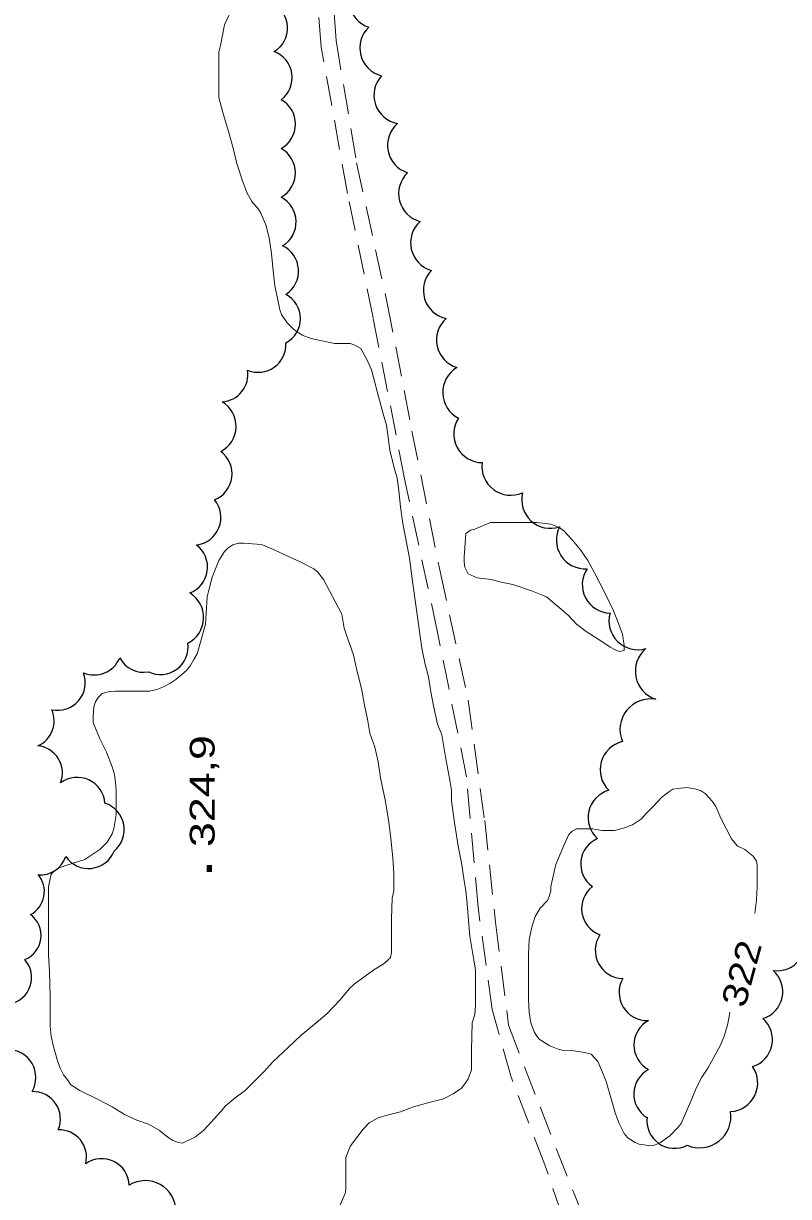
# Model space of a CAD drawing. Extents: x 240591 to 242335, y 5323482 to 5326937.
# Drawn here: x 241626.7 to 241719.3, y 5325779.2 to 5325921.4 of the extents above; entities that cross this region are included whole.
import ezdxf

# ---------------------------------------------------------------- set-up
doc = ezdxf.new("R2010")
doc.units = 0
doc.header["$LTSCALE"] = 1.2
doc.linetypes.add('MEDIUM_DASHED', pattern=[4.5, 3, -1.5])
for name, color, linetype, lineweight in [('19', 7, 'Continuous', 13), ('2', 7, 'Continuous', 13), ('3', 7, 'Continuous', 140), ('44', 7, 'Continuous', 25)]:
    doc.layers.add(name, color=color, linetype=linetype, lineweight=lineweight)

msp = doc.modelspace()

# ---------------------------------------------------------------- linework, layer by layer
at = {"layer": '19', "linetype": 'MEDIUM_DASHED'}
for points in [[(241695.4, 5325766.6), (241689.8, 5325783.1), (241685.7, 5325793.7), (241683.4, 5325801.9), (241681.7, 5325814.3), (241680.3, 5325830.1), (241676.8, 5325847.6), (241672.8, 5325866.2), (241669, 5325885.7), (241665.9, 5325900.8), (241662.7, 5325918.5), (241661.5, 5325935.1), (241659.9, 5325951.9), (241658.8, 5325968), (241656.9, 5325986.2), (241654.9, 5326006.1), (241652.6, 5326024.1), (241650, 5326039.6), (241647, 5326053.6), (241643.4, 5326064.5), (241638.5, 5326075.3), (241632.4, 5326086.8), (241627, 5326097.8)], [(241663.5, 5325933.4), (241664.5, 5325919.3), (241667, 5325904.5), (241670.7, 5325887.5), (241673.7, 5325872), (241677.1, 5325855), (241680.5, 5325839.4), (241682.5, 5325824.8), (241683.8, 5325812.5), (241685.4, 5325800), (241689.2, 5325790.1), (241693.4, 5325779.4), (241696.7, 5325771.1), (241698.6, 5325766.6)]]:
    msp.add_lwpolyline(points, dxfattribs=at)
at = {"layer": '2'}
for points in [[(241664.3, 5325882.6), (241661.5, 5325883.2), (241660.4, 5325883.6), (241659.4, 5325884.3), (241658.6, 5325885.1), (241657.9, 5325886.1), (241657.7, 5325886.7), (241657.4, 5325888.1), (241657.1, 5325889.6), (241656.9, 5325891.4), (241656.7, 5325893.5), (241656.4, 5325895.4), (241656, 5325897), (241655.4, 5325898.4), (241655.1, 5325898.9), (241654.3, 5325899.8), (241653.7, 5325900.9), (241653.2, 5325902.2), (241652.5, 5325904.4), (241652.1, 5325906.1), (241651.6, 5325907.9), (241650.8, 5325910.6), (241650.3, 5325912.4), (241650.3, 5325913.3), (241650.3, 5325915.2), (241650.3, 5325917.9), (241650.5, 5325918.7), (241651, 5325921.2), (241651.6, 5325922.5)], [(241664.6, 5325777.3), (241665.6, 5325779.6), (241665.7, 5325780.1), (241665.7, 5325781.4), (241665.7, 5325784), (241666.2, 5325785.3), (241666.5, 5325785.7), (241667.8, 5325787.4), (241668.5, 5325788.2), (241669.6, 5325788.8), (241670.7, 5325789.1), (241672.3, 5325789.5), (241673.9, 5325790.1), (241675.9, 5325790.7), (241677.5, 5325791.1), (241678.7, 5325791.7), (241679.7, 5325792.4), (241680.1, 5325792.9), (241680.5, 5325793.5), (241680.9, 5325794.6), (241680.9, 5325795.3), (241680.9, 5325797), (241681, 5325800.3), (241681.3, 5325801.3), (241681.4, 5325802.4), (241681.4, 5325803.7), (241681.4, 5325806.7), (241681.2, 5325807.9), (241680.7, 5325810.8), (241680.6, 5325812.2), (241680.4, 5325814.7), (241680.2, 5325816.3), (241680, 5325817.5), (241679.7, 5325819.7), (241679.3, 5325821.7), (241678.8, 5325824.8), (241678.5, 5325827.2), (241678.5, 5325828.5), (241678.3, 5325829.7), (241677.8, 5325832.3), (241677.3, 5325835.2), (241676.8, 5325836.5), (241676.3, 5325838.7), (241676, 5325840.4), (241675.7, 5325842.2), (241675.3, 5325843.7), (241674.9, 5325845.7), (241674.7, 5325847.1), (241674.4, 5325849.2), (241674.2, 5325850.6), (241673.8, 5325853.5), (241673.4, 5325856.6), (241673.1, 5325858.1), (241672.6, 5325860.8), (241672.3, 5325862.8), (241672.1, 5325864.8), (241671.9, 5325866.3), (241671.5, 5325867.7), (241671, 5325869.7), (241670.8, 5325871.2), (241670.6, 5325872.7), (241670.2, 5325874.1), (241669.5, 5325876.8), (241668.8, 5325879.4), (241668.3, 5325880.5), (241667.5, 5325882), (241666.8, 5325882.4), (241666.2, 5325882.6), (241665.4, 5325882.6), (241664.3, 5325882.6)], [(241646.4, 5325843), (241646.9, 5325843.6), (241647.3, 5325844.3), (241647.7, 5325845), (241648.1, 5325846.4), (241648.7, 5325848.6), (241648.8, 5325849.9), (241648.9, 5325851.9), (241649.1, 5325852.7), (241649.5, 5325854.3), (241650.3, 5325856.3), (241651, 5325857.4), (241651.4, 5325857.8), (241652, 5325858.2), (241652.7, 5325858.4), (241653.4, 5325858.4), (241654.9, 5325858.3), (241655.6, 5325858.2), (241657, 5325857.6), (241658.9, 5325856.7), (241660.1, 5325856.2), (241661.8, 5325855.3), (241662.3, 5325854.9), (241663, 5325854), (241665.2, 5325849.8)], [(241665.2, 5325849.8), (241665.5, 5325848.1), (241665.7, 5325847.5), (241666.6, 5325844.9), (241667, 5325843.2), (241667.6, 5325840.8), (241668, 5325838.6), (241668.3, 5325837.1), (241668.6, 5325835.4), (241669.2, 5325833.7), (241669.6, 5325831.9), (241669.9, 5325830), (241670.5, 5325827.1), (241670.9, 5325824.6), (241671.1, 5325823), (241671.4, 5325820.3), (241671.5, 5325818.4), (241671.5, 5325816.3), (241671.3, 5325815.4), (241671.2, 5325812.9), (241671.2, 5325811.5), (241671.2, 5325810.1), (241671.2, 5325808.8), (241671.1, 5325808.2), (241670.7, 5325807.8), (241670.2, 5325807.4), (241669.1, 5325806.7), (241666.7, 5325805), (241666.1, 5325804.4), (241665, 5325803.1), (241663.4, 5325801.4), (241662.1, 5325800.3), (241660.3, 5325798.8), (241658.7, 5325797.3), (241656.9, 5325795.6), (241655.8, 5325794.4), (241653.5, 5325792.1), (241652.3, 5325791.2), (241651.1, 5325790.2), (241650.6, 5325789.6), (241648.5, 5325787.3), (241647.5, 5325786.5), (241645.9, 5325785.7), (241645.4, 5325785.8), (241644.7, 5325786.1), (241644.2, 5325786.4), (241643.1, 5325787.3), (241641.8, 5325788), (241640.4, 5325788.5), (241638.9, 5325789.2), (241637.4, 5325790.1), (241635.7, 5325791), (241633.5, 5325792.1), (241632.4, 5325792.8), (241632, 5325793.4), (241631.5, 5325794), (241631.1, 5325794.8), (241630.8, 5325795.7), (241630.2, 5325797.7), (241630, 5325798.7), (241629.9, 5325799.9), (241629.9, 5325801), (241629.9, 5325803.4), (241629.8, 5325806.5), (241629.7, 5325808.5), (241629.7, 5325810.8), (241629.7, 5325813.3), (241629.7, 5325816.8), (241630, 5325818.3), (241630.5, 5325818.8), (241631.1, 5325819.1), (241631.9, 5325819.4), (241634.1, 5325820.1), (241634.7, 5325820.5), (241635.9, 5325821.3), (241636.8, 5325822.2), (241637.4, 5325823.2), (241637.6, 5325823.8), (241637.9, 5325825.5), (241637.9, 5325826.5), (241637.9, 5325828.5), (241637.8, 5325829.4), (241637.7, 5325830.4), (241637.4, 5325831.3), (241636.7, 5325833.1), (241635.9, 5325834.7), (241635.1, 5325836.7), (241635.1, 5325837.4), (241635.2, 5325838.6), (241635.4, 5325839.2), (241635.7, 5325839.7), (241636.2, 5325840.2), (241636.9, 5325840.4), (241637.8, 5325840.5), (241638.8, 5325840.5), (241641.9, 5325840.5), (241642.8, 5325840.7), (241643.6, 5325841), (241644.4, 5325841.4), (241645.1, 5325841.9), (241646.4, 5325843)], [(241691.1, 5325819.5), (241692.1, 5325821.8), (241692.7, 5325823.1), (241693.1, 5325823.5), (241693.6, 5325823.8), (241694.2, 5325823.8), (241695.6, 5325823.8), (241696.7, 5325823.6), (241698.2, 5325823.6), (241699.3, 5325823.9), (241700.4, 5325824.3), (241701.5, 5325825), (241702, 5325825.6), (241702.9, 5325826.5), (241703.9, 5325827.6), (241704.8, 5325828.3), (241705.3, 5325828.6), (241705.9, 5325828.7), (241707, 5325828.8), (241708.1, 5325828.6), (241708.7, 5325828.4), (241709.2, 5325828.1), (241710.1, 5325827.1), (241710.5, 5325826.5), (241711.1, 5325825.1), (241712.4, 5325822.6), (241713.1, 5325821.7), (241713.6, 5325821.5), (241714, 5325821.3), (241715, 5325820.5), (241715.4, 5325819.9), (241715.5, 5325819.4), (241715.5, 5325818.8), (241715.5, 5325816.8), (241715.4, 5325815.2), (241715.2, 5325813.6)], [(241712.2, 5325801.6), (241712.2, 5325801.5), (241711.9, 5325800), (241711.5, 5325798.7), (241711, 5325797.5), (241710.4, 5325796.4), (241709.5, 5325794.8), (241708.8, 5325793.7), (241708.1, 5325792.4), (241707.6, 5325791.1), (241706.3, 5325788.1), (241705.9, 5325787.6), (241704.9, 5325786.6), (241703.8, 5325785.8), (241703.2, 5325785.5), (241702.6, 5325785.4), (241701.2, 5325785.6), (241700.7, 5325785.8), (241699.8, 5325786.4), (241699.4, 5325786.9), (241698.8, 5325788.1), (241698.3, 5325789.4), (241697.8, 5325791.1), (241697.2, 5325793.2), (241696.7, 5325794.5), (241696.2, 5325795.6), (241695.4, 5325796.5), (241694.6, 5325796.7), (241693.3, 5325796.9), (241691.9, 5325797), (241691.4, 5325797.1), (241690.4, 5325797.5), (241689.1, 5325798.3), (241688.8, 5325798.7), (241688.5, 5325799.2), (241688.1, 5325800.3), (241687.9, 5325801.6), (241687.8, 5325803.1), (241687.8, 5325805.8), (241687.8, 5325808.6), (241687.9, 5325810.4), (241688.2, 5325811.9), (241688.6, 5325813.2), (241689.2, 5325814.2), (241690.1, 5325815.1), (241690.3, 5325815.6), (241690.5, 5325816.3), (241690.5, 5325816.8), (241691.1, 5325819.5)]]:
    msp.add_lwpolyline(points, dxfattribs=at)
msp.add_lwpolyline([(241683.2, 5325860.9), (241686.2, 5325860.9), (241688.8, 5325860.9), (241690.5, 5325860.7), (241691.5, 5325860.3), (241692.1, 5325859.9), (241693.1, 5325858.8), (241694.1, 5325857.6), (241695, 5325856.3), (241695.8, 5325854.8), (241697.1, 5325852.3), (241698.1, 5325850.2), (241698.5, 5325849.2), (241699.2, 5325847.4), (241699.4, 5325846), (241699.4, 5325845.4), (241698.8, 5325845.3), (241698.3, 5325845.5), (241697.7, 5325845.8), (241696.7, 5325846.5), (241694.8, 5325847.7), (241693.6, 5325848.6), (241692.6, 5325849.7), (241691.5, 5325850.6), (241690, 5325851.9), (241689.5, 5325852.1), (241688.3, 5325852.6), (241685.9, 5325853.4), (241684.5, 5325853.7), (241683.3, 5325854), (241681.6, 5325854.2), (241680.5, 5325854.7), (241680.1, 5325855.5), (241680, 5325856.1), (241680, 5325856.7), (241680.2, 5325859.6), (241680.8, 5325860), (241681.3, 5325860.1)], close=True, dxfattribs=at)
at = {"layer": '3'}
msp.add_line((241649.2, 5325818.6), (241649.2, 5325819.4), dxfattribs=at)
at = {"layer": '44'}
for centre, radius, start, end in [((241655.273, 5325920.851), 3.37, 301.2317, 63.24073), ((241655.824, 5325914.819), 3.371, 307.37638, 69.2139), ((241656.221, 5325909.191), 3.379, 298.82427, 60.78794), ((241678.562, 5325889.036), 3.484, 135.91357, 257.86323), ((241697.781, 5325853.402), 3.464, 146.57597, 268.33257), ((241644.993, 5325849.401), 3.479, 296.95194, 58.90346), ((241697.616, 5325814.138), 3.376, 127.94394, 249.79939), ((241699.321, 5325809.09), 3.431, 146.7821, 268.48566), ((241712.087, 5325793.007), 3.472, 273.0196, 35.03161), ((241641.417, 5325777.462), 3.712, 359.84043, 121.65575)]:
    msp.add_arc(centre, radius, start, end, dxfattribs=at)
for centre, major_axis, ratio, start_param, end_param in [((241669.567, 5325924.254), (-3.437, -0.664), 0.999914, 5.222315, 7.3443477), ((241670.871, 5325918.41), (-3.37, -0.884), 0.998787, 5.2166094, 7.3451129), ((241672.587, 5325912.695), (-3.306, -1.128), 0.999464, 5.2177939, 7.344857), ((241674.223, 5325906.617), (-3.412, -0.7), 0.998619, 5.2175384, 7.3447903), ((241656.219, 5325903.28), (-1.712, 2.903), 0.999994, 3.1136591, 5.2452973), ((241675.564, 5325900.77), (-3.373, -0.875), 0.999655, 5.216245, 7.3436877), ((241656.298, 5325897.335), (3.333, -0.521), 0.999879, 5.4067102, 7.5311012), ((241677.014, 5325894.812), (-3.482, -0.152), 0.999887, 5.4024649, 7.5328772), ((241656.585, 5325891.383), (3.381, -0.078), 0.999478, 5.3121956, 7.4356511), ((241656.838, 5325885.619), (3.286, -0.67), 0.99424, 5.4072582, 7.5593248), ((241680.14, 5325883.029), (-3.44, -0.537), 0.999009, 5.2832907, 7.4050858), ((241655.079, 5325882.471), (2.85, 1.775), 0.999936, 3.7643197, 5.7881384), ((241650.502, 5325878.875), (1.389, 3.039), 0.999984, 3.632633, 5.2929664), ((241680.952, 5325876.684), (1.888, -2.975), 0.999995, 3.119423, 5.2427392), ((241648.96, 5325872.577), (3.32, -0.904), 0.999928, 5.4552107, 7.5863451), ((241682.191, 5325871.616), (1.622, -3.051), 0.987279, 3.6329628, 5.7918151), ((241648.51, 5325866.805), (3.37, -0.491), 0.993977, 5.2449535, 7.3591549), ((241685.627, 5325867.65), (3.389, -0.728), 0.988943, 3.2032113, 5.3544947), ((241690.408, 5325863.68), (0.9, -3.351), 0.986855, 4.2057384, 6.3539764), ((241647.182, 5325861.538), (3.138, -1.247), 0.999793, 5.2207092, 7.3451526), ((241694.599, 5325858.74), (1.862, -2.907), 0.98731, 3.6317156, 5.7930624), ((241645.567, 5325855.519), (3.355, -0.44), 0.994106, 5.2117658, 7.3318461), ((241701.057, 5325849.01), (-2.538, -2.428), 0.996247, 5.2497276, 7.3678992), ((241643.249, 5325845.839), (2.706, 1.979), 0.999984, 3.63496, 5.789818), ((241704.318, 5325842.907), (-3.508, -0.698), 0.999995, 5.2175262, 7.3484633), ((241635.219, 5325845.804), (3.328, 0.428), 0.999868, 4.1867711, 5.7559139), ((241641.274, 5325846.061), (-2.962, -1.562), 0.980199, 6.2822868, 7.5356554), ((241630.792, 5325841.507), (2.081, -2.629), 0.999277, 5.4021626, 7.5518387), ((241702.64, 5325835.795), (-2.903, 2.396), 0.995679, 5.2425187, 7.3646998), ((241627.026, 5325836.897), (2.486, -2.253), 0.995305, 5.8752573, 7.431563), ((241700.003, 5325830.956), (-3.395, 0.939), 0.996945, 5.2204562, 7.3403549), ((241628.042, 5325830.561), (3.121, 1.207), 0.994349, 5.5462871, 7.3733003), ((241633.166, 5325826.695), (-2.74, -1.933), 0.996787, 2.5868028, 4.7412835), ((241698.538, 5325825.15), (-3.424, 0.771), 0.986187, 5.2253796, 7.3310617), ((241635.507, 5325823.696), (-0.642, 3.295), 0.999741, 3.6375744, 5.7872034), ((241697.483, 5325819.529), (-3.344, 0.341), 0.99544, 5.2148735, 7.3389089), ((241628.75, 5325821.406), (3.123, 0.585), 0.999352, 4.4235776, 5.7880613), ((241634.53, 5325822.337), (3.324, 0.376), 0.999424, 3.6321635, 5.7926144), ((241626.019, 5325816.205), (0, 3.179), 0.997812, 3.6381264, 5.4160312), ((241625.629, 5325810.888), (3.153, -0.382), 0.992435, 5.2130134, 7.3318838), ((241717.943, 5325809.974), (1.339, 3.09), 0.995043, 3.3927024, 5.5536282), ((241624.432, 5325805.787), (3.06, -1.01), 0.99937, 5.2146205, 7.3426674), ((241715.226, 5325804.077), (-0.256, 3.375), 0.994215, 3.3529044, 5.5009687), ((241702.144, 5325803.956), (1.761, -2.882), 0.998412, 3.6355005, 5.7892775), ((241703.916, 5325797.631), (-1.961, -2.744), 0.992664, 4.2575368, 6.4153154), ((241713.933, 5325798.263), (3.217, -1.137), 0.999758, 5.3486081, 7.4748305), ((241624.796, 5325793.674), (2.904, 1.706), 0.999532, 5.2214239, 7.3457237), ((241703.92, 5325791.694), (-1.682, -2.927), 0.993841, 4.1585756, 6.2510815), ((241627.802, 5325788.637), (-1.661, 2.892), 0.99942, 3.7890432, 5.792174), ((241705.5, 5325788.454), (-1.677, -2.925), 0.994333, 5.1093331, 7.276148), ((241708.51, 5325788.96), (1.859, -3.319), 0.99986, 5.3700237, 7.4965275), ((241630.962, 5325784.007), (-2.486, 2.218), 0.999419, 3.6324551, 5.4707343), ((241636.136, 5325780.506), (-2.991, 1.476), 0.999594, 3.6347673, 5.7900106)]:
    msp.add_ellipse(centre, major_axis=major_axis, ratio=ratio, start_param=start_param, end_param=end_param, dxfattribs=at)

# ---------------------------------------------------------------- texts
at = {"layer": '2', "width": 1.2}
msp.add_text('322', height=3, rotation=74.874, dxfattribs=at).set_placement((241714, 5325802))
at = {"layer": '3', "width": 1.35}
msp.add_text('324,9', height=3, rotation=90, dxfattribs=at).set_placement((241649.8, 5325821.6))

doc.saveas('drawing.dxf')
